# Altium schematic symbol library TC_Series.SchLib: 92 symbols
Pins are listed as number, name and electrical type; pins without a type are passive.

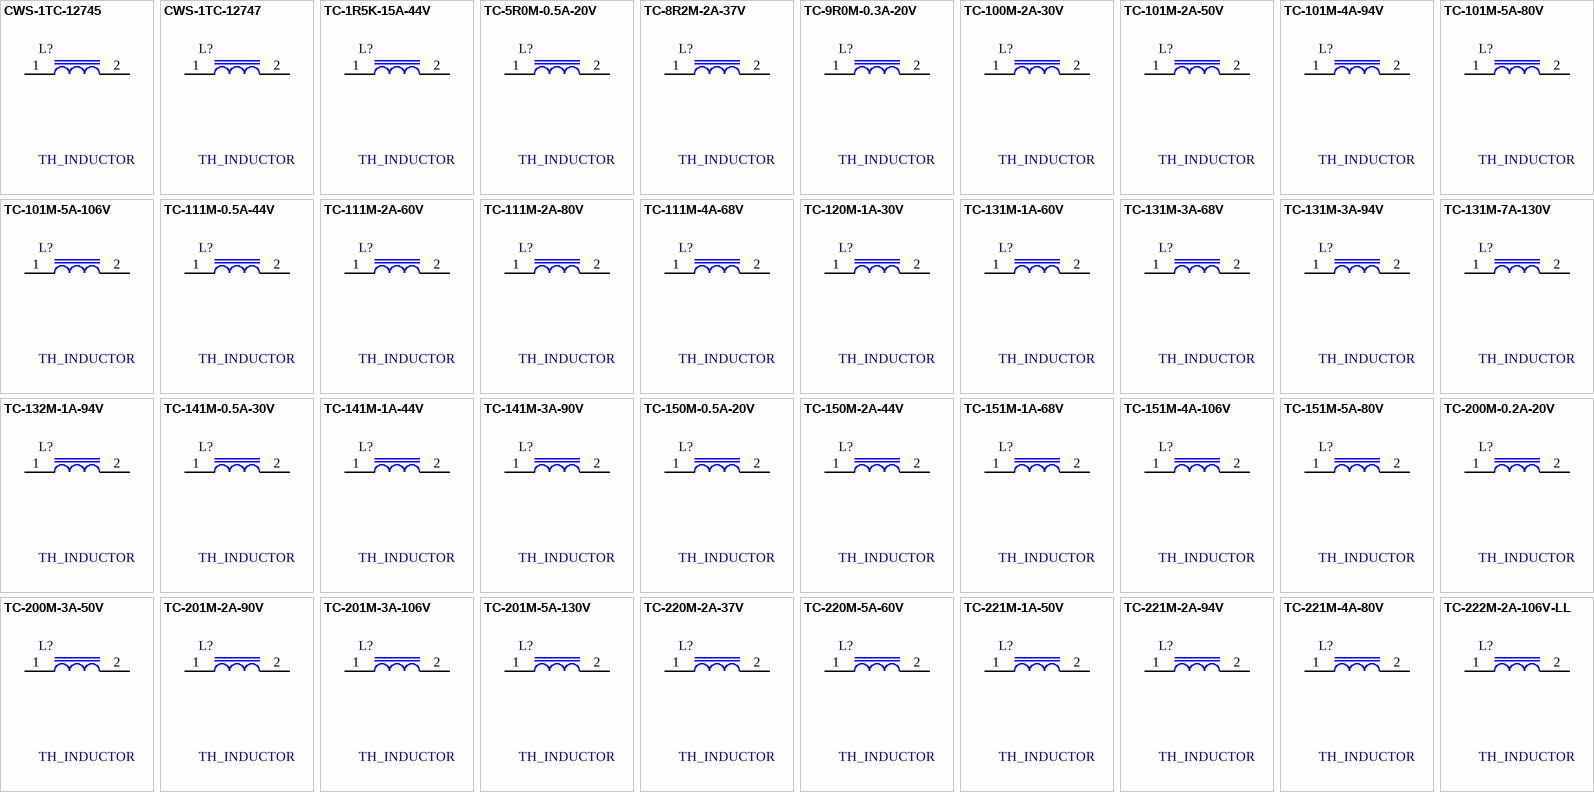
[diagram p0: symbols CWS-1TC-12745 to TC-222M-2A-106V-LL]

## CWS-1TC-12745
designator L?, comment TH_INDUCTOR
POWER INDUCTOR 1 A, 220 uH, 200 mOhms, OD 17.6 mm, HT 8.63 mm; Manufacturer #1: CWS; OD: 17.6 mm; Current: 1 A; Inductance: 220 uH
footprint CWS-1TC-12745
pins: 1, 2

## CWS-1TC-12747
designator L?, comment TH_INDUCTOR
POWER INDUCTOR 1 A, 680 uH, 330 mOhms, OD 18.52 mm, HT 10.87 mm; Manufacturer #1: CWS; Current: 1 A; Inductance: 680 uH
footprint CWS-1TC-12747
pins: 1, 2

## TC-1R5K-15A-44V
designator L?, comment TH_INDUCTOR
POWER INDUCTOR 15 A, 1.5 uH, 2 mOhms, OD 17 mm, HT 11 mm; Manufacturer #1: CWS; OD: 17 mm; Current: 15 A; DCR: 2 mOhms; Inductance: 1.5 uH
footprint TC-1R5K-15A-44V
pins: 1, 2

## TC-5R0M-0.5A-20V
designator L?, comment TH_INDUCTOR
POWER INDUCTOR 0.5 A, 5 uH, 63 mOhms, OD 7 mm, HT 3 mm; Manufacturer #1: CWS; OD: 7 mm; Current: 0.5 A; Inductance: 5 uH
footprint TC-5R0M-0.5A-20V
pins: 1, 2

## TC-8R2M-2A-37V
designator L?, comment TH_INDUCTOR
POWER INDUCTOR 2 A, 8.2 uH, 13 mOhms, OD 12 mm, HT 6 mm; Manufacturer #1: CWS; OD: 12 mm; Current: 2 A; Inductance: 8.2 uH
footprint TC-8R2M-2A-37V
pins: 1, 2

## TC-9R0M-0.3A-20V
designator L?, comment TH_INDUCTOR
POWER INDUCTOR 0.3 A, 9 uH, 95 mOhms, OD 7 mm, HT 3 mm; Manufacturer #1: CWS; OD: 7 mm; Current: 0.3 A; Inductance: 9 uH
footprint TC-9R0M-0.3A-20V
pins: 1, 2

## TC-100M-2A-30V
designator L?, comment TH_INDUCTOR
POWER INDUCTOR 2 A, 10 uH, 24 mOhms, OD 10 mm, HT 6 mm; Manufacturer #1: CWS; OD: 10 mm; Current: 2 A; Inductance: 10 uH
footprint TC-100M-2A-30V
pins: 1, 2

## TC-101M-2A-50V
designator L?, comment TH_INDUCTOR
POWER INDUCTOR 2 A, 100 uH, 99 mOhms, OD 15 mm, HT 8 mm; Manufacturer #1: CWS; OD: 15 mm; Current: 2 A; Inductance: 100 uH
footprint TC-101M-2A-50V
pins: 1, 2

## TC-101M-4A-94V
designator L?, comment TH_INDUCTOR
POWER INDUCTOR 4 A, 100 uH, 27 mOhms, OD 28 mm, HT 13 mm; Manufacturer #1: CWS; OD: 28 mm; Current: 4 A; Inductance: 100 uH
footprint TC-101M-4A-94V
pins: 1, 2

## TC-101M-5A-80V
designator L?, comment TH_INDUCTOR
POWER INDUCTOR 5 A, 100 uH, 38 mOhms, OD 24 mm, HT 11 mm; Manufacturer #1: CWS; OD: 24 mm; Current: 5 A; Inductance: 100 uH
footprint TC-101M-5A-80V
pins: 1, 2

## TC-101M-5A-106V
designator L?, comment TH_INDUCTOR
POWER INDUCTOR 5 A, 100 uH, 22 mOhms, OD 31 mm, HT 16 mm; Manufacturer #1: CWS; OD: 31 mm; Current: 5 A; Inductance: 100 uH
footprint TC-101M-5A-106V
pins: 1, 2

## TC-111M-0.5A-44V
designator L?, comment TH_INDUCTOR
POWER INDUCTOR 0.5 A, 110 uH, 149 mOhms, OD 13 mm, HT 6 mm; Manufacturer #1: CWS; OD: 13 mm; Current: 0.5 A; Inductance: 110 uH
footprint TC-111M-0.5A-44V
pins: 1, 2

## TC-111M-2A-60V
designator L?, comment TH_INDUCTOR
POWER INDUCTOR 2 A, 110 uH, 67 mOhms, OD 18 mm, HT 10 mm; Manufacturer #1: CWS; OD: 18 mm; Current: 2 A; Inductance: 110 uH
footprint TC-111M-2A-60V
pins: 1, 2

## TC-111M-2A-80V
designator L?, comment TH_INDUCTOR
POWER INDUCTOR 2 A, 110 uH, 40 mOhms, OD 23 mm, HT 9 mm; Manufacturer #1: CWS; OD: 23 mm; Current: 2 A; Inductance: 110 uH
footprint TC-111M-2A-80V
pins: 1, 2

## TC-111M-4A-68V
designator L?, comment TH_INDUCTOR
POWER INDUCTOR 4 A, 110 uH, 56 mOhms, OD 21 mm, HT 9 mm; Manufacturer #1: CWS; OD: 21 mm; Current: 4 A; Inductance: 110 uH
footprint TC-111M-4A-68V
pins: 1, 2

## TC-120M-1A-30V
designator L?, comment TH_INDUCTOR
POWER INDUCTOR 1 A, 12 uH, 28 mOhms, OD 9.5 mm, HT 5 mm; Manufacturer #1: CWS; OD: 9.5 mm; Current: 1 A; Inductance: 12 uH
footprint TC-120M-1A-30V
pins: 1, 2

## TC-131M-1A-60V
designator L?, comment TH_INDUCTOR
POWER INDUCTOR 1 A, 130 uH, 78 mOhms, OD 17 mm, HT 8 mm; Manufacturer #1: CWS; OD: 17 mm; Current: 1 A; Inductance: 130 uH
footprint TC-131M-1A-60V
pins: 1, 2

## TC-131M-3A-68V
designator L?, comment TH_INDUCTOR
POWER INDUCTOR 3 A, 130 uH, 73 mOhms, OD 21 mm, HT 9 mm; Manufacturer #1: CWS; OD: 21 mm; Current: 3 A; Inductance: 130 uH
footprint TC-131M-3A-68V
pins: 1, 2

## TC-131M-3A-94V
designator L?, comment TH_INDUCTOR
POWER INDUCTOR 3 A, 130 uH, 32 mOhms, OD 28.5 mm, HT 13 mm; Manufacturer #1: CWS; OD: 28.5 mm; Current: 3 A; Inductance: 130 uH
footprint TC-131M-3A-94V
pins: 1, 2

## TC-131M-7A-130V
designator L?, comment TH_INDUCTOR
POWER INDUCTOR 7 A, 130 uH, 24 mOhms, OD 38 mm, HT 16 mm; Manufacturer #1: CWS; OD: 38 mm; Current: 7 A; Inductance: 130 uH
footprint TC-131M-7A-130V
pins: 1, 2

## TC-132M-1A-94V
designator L?, comment TH_INDUCTOR
POWER INDUCTOR 1 A, 1300 uH, 396 mOhms, OD 27 mm, HT 11 mm; Manufacturer #1: CWS; OD: 27 mm; Current: 1 A; Inductance: 1300 uH
footprint TC-132M-1A-94V
pins: 1, 2

## TC-141M-0.5A-30V
designator L?, comment TH_INDUCTOR
POWER INDUCTOR 0.5 A, 140 uH, 52 mOhms, OD 9.5 mm, HT 5 mm; Manufacturer #1: CWS; OD: 9.5 mm; Current: 0.5 A; Inductance: 140 uH
footprint TC-141M-0.5A-30V
pins: 1, 2

## TC-141M-1A-44V
designator L?, comment TH_INDUCTOR
POWER INDUCTOR 1 A, 140 uH, 282 mOhms, OD 13 mm, HT 6.5 mm; Manufacturer #1: CWS; OD: 13 mm; Current: 1 A; Inductance: 140 uH
footprint TC-141M-1A-44V
pins: 1, 2

## TC-141M-3A-90V
designator L?, comment TH_INDUCTOR
POWER INDUCTOR 3 A, 140 uH, 36 mOhms, OD 26 mm, HT 12 mm; Manufacturer #1: CWS; OD: 26 mm; Current: 3 A; Inductance: 140 uH
footprint TC-141M-3A-90V
pins: 1, 2

## TC-150M-0.5A-20V
designator L?, comment TH_INDUCTOR
POWER INDUCTOR 0.5 A, 15 uH, 158 mOhms, OD 6 mm, HT 3 mm; Manufacturer #1: CWS; OD: 6 mm; Current: 0.5 A; Inductance: 15 uH
footprint TC-150M-0.5A-20V
pins: 1, 2

## TC-150M-2A-44V
designator L?, comment TH_INDUCTOR
POWER INDUCTOR 2 A, 15 uH, 17 mOhms, OD 13 mm, HT 6.5 mm; Manufacturer #1: CWS; OD: 13 mm; Current: 2 A; Inductance: 15 uH
footprint TC-150M-2A-44V
pins: 1, 2

## TC-151M-1A-68V
designator L?, comment TH_INDUCTOR
POWER INDUCTOR 1 A, 150 uH, 75 mOhms, OD 21 mm, HT 8 mm; Manufacturer #1: CWS; OD: 21 mm; Current: 1 A; Inductance: 150 uH
footprint TC-151M-1A-68V
pins: 1, 2

## TC-151M-4A-106V
designator L?, comment TH_INDUCTOR
POWER INDUCTOR 4 A, 150 uH, 33 mOhms, OD 31 mm, HT 16 mm; Manufacturer #1: CWS; OD: 31 mm; Current: 4 A; Inductance: 150 uH
footprint TC-151M-4A-106V
pins: 1, 2

## TC-151M-5A-80V
designator L?, comment TH_INDUCTOR
POWER INDUCTOR 5 A, 150 uH, 38 mOhms, OD 24 mm, HT 11 mm; Manufacturer #1: CWS; OD: 24 mm; Current: 5 A; Inductance: 150 uH
footprint TC-151M-5A-80V
pins: 1, 2

## TC-200M-0.2A-20V
designator L?, comment TH_INDUCTOR
POWER INDUCTOR 0.2 A, 20 uH, 190 mOhms, OD 6 mm, HT 3 mm; Manufacturer #1: CWS; OD: 6 mm; Current: 0.2 A; Inductance: 20 uH
footprint TC-200M-0.2A-20V
pins: 1, 2

## TC-200M-3A-50V
designator L?, comment TH_INDUCTOR
POWER INDUCTOR 3 A, 20 uH, 18 mOhms, OD 15 mm, HT 7 mm; Manufacturer #1: CWS; OD: 15 mm; Current: 3 A; Inductance: 20 uH
footprint TC-200M-3A-50V
pins: 1, 2

## TC-201M-2A-90V
designator L?, comment TH_INDUCTOR
POWER INDUCTOR 2 A, 200 uH, 52 mOhms, OD 26 mm, HT 12 mm; Manufacturer #1: CWS; OD: 26 mm; Current: 2 A; Inductance: 200 uH
footprint TC-201M-2A-90V
pins: 1, 2

## TC-201M-3A-106V
designator L?, comment TH_INDUCTOR
POWER INDUCTOR 3 A, 200 uH, 46 mOhms, OD 31 mm, HT 15 mm; Manufacturer #1: CWS; OD: 31 mm; Current: 3 A; Inductance: 200 uH
footprint TC-201M-3A-106V
pins: 1, 2

## TC-201M-5A-130V
designator L?, comment TH_INDUCTOR
POWER INDUCTOR 5 A, 200 uH, 30 mOhms, OD 38.5 mm, HT 17.5 mm; Manufacturer #1: CWS; OD: 38.5 mm; Current: 5 A; Inductance: 200 uH
footprint TC-201M-5A-130V
pins: 1, 2

## TC-220M-2A-37V
designator L?, comment TH_INDUCTOR
POWER INDUCTOR 2 A, 22 uH, 47 mOhms, OD 12 mm, HT 5.5 mm; Manufacturer #1: CWS; OD: 12 mm; Current: 2 A; Inductance: 22 uH
footprint TC-220M-2A-37V
pins: 1, 2

## TC-220M-5A-60V
designator L?, comment TH_INDUCTOR
POWER INDUCTOR 5 A, 22 uH, 13 mOhms, OD 18 mm, HT 10 mm; Manufacturer #1: CWS; OD: 18 mm; Current: 5 A; Inductance: 22 uH
footprint TC-220M-5A-60V
pins: 1, 2

## TC-221M-1A-50V
designator L?, comment TH_INDUCTOR
POWER INDUCTOR 1 A, 220 uH, 145 mOhms, OD 14 mm, HT 7 mm; Manufacturer #1: CWS; OD: 14 mm; Current: 1 A; Inductance: 220 uH
footprint TC-221M-1A-50V
pins: 1, 2

## TC-221M-2A-94V
designator L?, comment TH_INDUCTOR
POWER INDUCTOR 2 A, 220 uH, 60 mOhms, OD 27 mm, HT 12 mm; Manufacturer #1: CWS; OD: 27 mm; Current: 2 A; Inductance: 220 uH
footprint TC-221M-2A-94V
pins: 1, 2

## TC-221M-4A-80V
designator L?, comment TH_INDUCTOR
POWER INDUCTOR 4 A, 220 uH, 49 mOhms, OD 24 mm, HT 11 mm; Manufacturer #1: CWS; OD: 24 mm; Current: 4 A; Inductance: 220 uH
footprint TC-221M-4A-80V
pins: 1, 2

## TC-222M-2A-106V-LL
designator L?, comment TH_INDUCTOR
POWER INDUCTOR 2 A, 2200 uH, 375 mOhms, OD 31 mm, HT 16 mm; Manufacturer #1: CWS; OD: 31 mm; Current: 2 A; Inductance: 2200 uH
footprint TC-222M-2A-106V-LL
pins: 1, 2

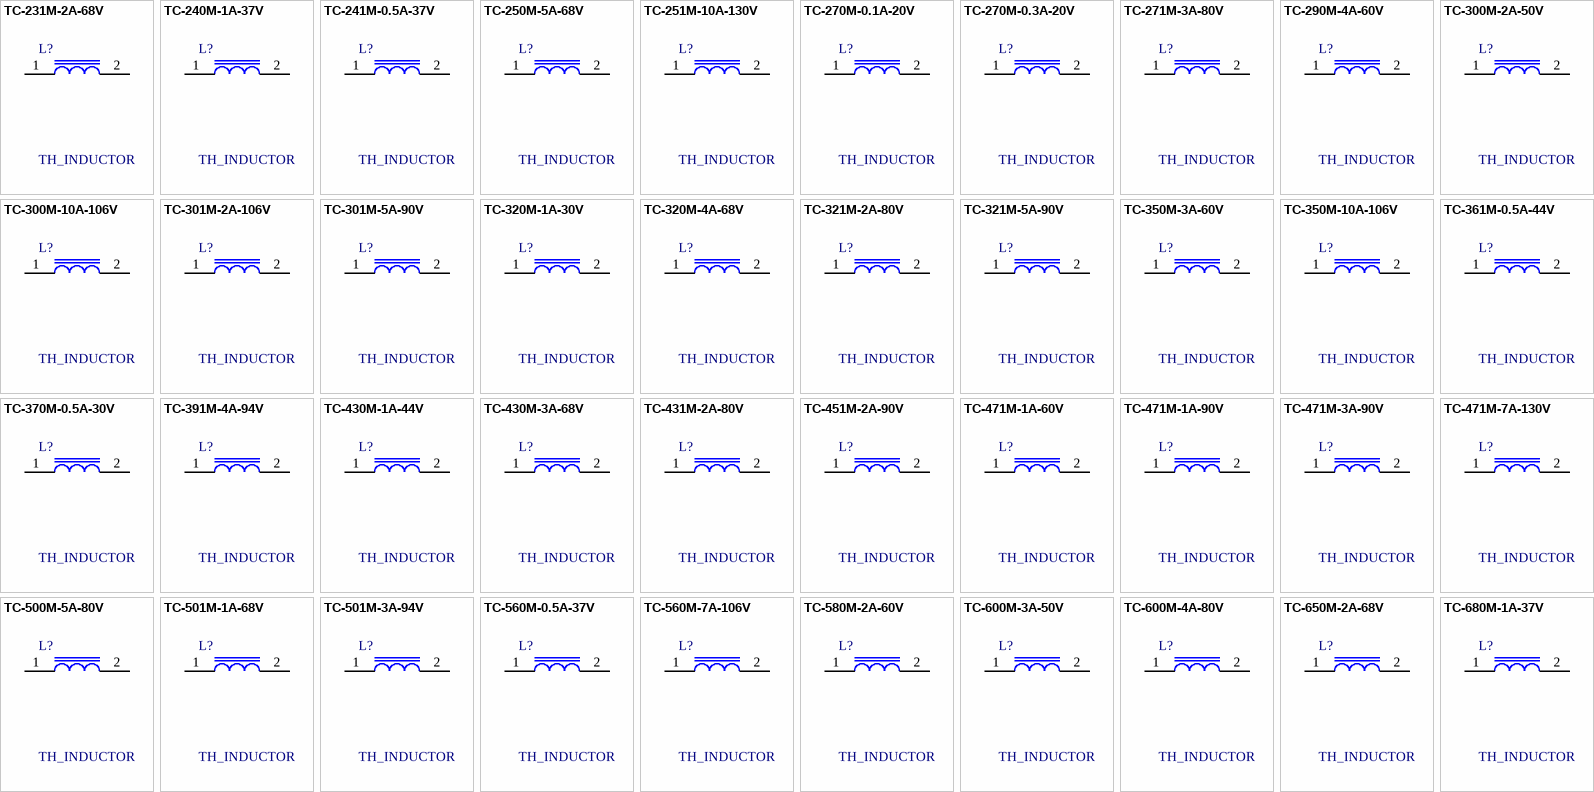
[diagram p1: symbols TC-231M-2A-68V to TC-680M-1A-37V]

## TC-231M-2A-68V
designator L?, comment TH_INDUCTOR
POWER INDUCTOR 2 A, 230 uH, 170 mOhms, OD 21 mm, HT 9 mm; Manufacturer #1: CWS; OD: 21 mm; Current: 2 A; Inductance: 230 uH
footprint TC-231M-2A-68V
pins: 1, 2

## TC-240M-1A-37V
designator L?, comment TH_INDUCTOR
POWER INDUCTOR 1 A, 24 uH, 47 mOhms, OD 11.5 mm, HT 5 mm; Manufacturer #1: CWS; OD: 11.5 mm; Current: 1 A; Inductance: 24 uH
footprint TC-240M-1A-37V
pins: 1, 2

## TC-241M-0.5A-37V
designator L?, comment TH_INDUCTOR
POWER INDUCTOR 0.5 A, 240 uH, 495 mOhms, OD 10.7 mm, HT 5.34 mm; Manufacturer #1: CWS; OD: 10.7 mm; Current: 0.5 A; Inductance: 240 uH
footprint TC-241M-0.5A-37V
pins: 1, 2

## TC-250M-5A-68V
designator L?, comment TH_INDUCTOR
POWER INDUCTOR 5 A, 25 uH, 14 mOhms, OD 21 mm, HT 8 mm; Manufacturer #1: CWS; OD: 21 mm; Current: 5 A; Inductance: 25 uH
footprint TC-250M-5A-68V
pins: 1, 2

## TC-251M-10A-130V
designator L?, comment TH_INDUCTOR
POWER INDUCTOR 10 A, 250 uH, 34 mOhms, OD 40 mm, HT 20 mm; Manufacturer #1: CWS; OD: 40 mm; Current: 10 A; Inductance: 250 uH
footprint TC-251M-10A-130V
pins: 1, 2

## TC-270M-0.1A-20V
designator L?, comment TH_INDUCTOR
POWER INDUCTOR 0.1 A, 27 uH, 255 mOhms, OD 6 mm, HT 2.8 mm; Manufacturer #1: CWS; OD: 6 mm; Current: 0.1 A; Inductance: 27 uH
footprint TC-270M-0.1A-20V
pins: 1, 2

## TC-270M-0.3A-20V
designator L?, comment TH_INDUCTOR
POWER INDUCTOR 0.3 A, 27 uH, 259 mOhms, OD 6 mm, HT 3 mm; Manufacturer #1: CWS; OD: 6 mm; Current: 0.3 A; Inductance: 27 uH
footprint TC-270M-0.3A-20V
pins: 1, 2

## TC-271M-3A-80V
designator L?, comment TH_INDUCTOR
POWER INDUCTOR 3 A, 270 uH, 114 mOhms, OD 24 mm, HT 11 mm; Manufacturer #1: CWS; OD: 24 mm; Current: 3 A; Inductance: 270 uH
footprint TC-271M-3A-80V
pins: 1, 2

## TC-290M-4A-60V
designator L?, comment TH_INDUCTOR
POWER INDUCTOR 4 A, 29 uH, 17 mOhms, OD 18 mm, HT 10 mm; Manufacturer #1: CWS; OD: 18 mm; Current: 4 A; Inductance: 29 uH
footprint TC-290M-4A-60V
pins: 1, 2

## TC-300M-2A-50V
designator L?, comment TH_INDUCTOR
POWER INDUCTOR 2 A, 30 uH, 26 mOhms, OD 15 mm, HT 7 mm; Manufacturer #1: CWS; OD: 15 mm; Current: 2 A; Inductance: 30 uH
footprint TC-300M-2A-50V
pins: 1, 2

## TC-300M-10A-106V
designator L?, comment TH_INDUCTOR
POWER INDUCTOR 10 A, 30 uH, 8 mOhms, OD 33 mm, HT 17 mm; Manufacturer #1: CWS; OD: 33 mm; Current: 10 A; DCR: 8 mOhms; Inductance: 30 uH
footprint TC-300M-10A-106V
pins: 1, 2

## TC-301M-2A-106V
designator L?, comment TH_INDUCTOR
POWER INDUCTOR 2 A, 300 uH, 70 mOhms, OD 32 mm, HT 15 mm; Manufacturer #1: CWS; OD: 32 mm; Current: 2 A; Inductance: 300 uH
footprint TC-301M-2A-106V
pins: 1, 2

## TC-301M-5A-90V
designator L?, comment TH_INDUCTOR
POWER INDUCTOR 5 A, 300 uH, 68 mOhms, OD 26 mm, HT 14 mm; Manufacturer #1: CWS; OD: 26 mm; Current: 5 A; Inductance: 300 uH
footprint TC-301M-5A-90V
pins: 1, 2

## TC-320M-1A-30V
designator L?, comment TH_INDUCTOR
POWER INDUCTOR 1 A, 32 uH, 93 mOhms, OD 9.5 mm, HT 5.5 mm; Manufacturer #1: CWS; OD: 9.5 mm; Current: 1 A; Inductance: 32 uH
footprint TC-320M-1A-30V
pins: 1, 2

## TC-320M-4A-68V
designator L?, comment TH_INDUCTOR
POWER INDUCTOR 4 A, 32 uH, 17 mOhms, OD 21 mm, HT 8 mm; Manufacturer #1: CWS; OD: 21 mm; Current: 4 A; Inductance: 32 uH
footprint TC-320M-4A-68V
pins: 1, 2

## TC-321M-2A-80V
designator L?, comment TH_INDUCTOR
POWER INDUCTOR 2 A, 320 uH, 157 mOhms, OD 23 mm, HT 10 mm; Manufacturer #1: CWS; OD: 23 mm; Current: 2 A; Inductance: 320 uH
footprint TC-321M-2A-80V
pins: 1, 2

## TC-321M-5A-90V
designator L?, comment TH_INDUCTOR
POWER INDUCTOR 5 A, 320 uH, 52 mOhms, OD 29.2 mm, HT 16.5 mm; Manufacturer #1: CWS; OD: 29.2 mm; Current: 5 A; Inductance: 320 uH
footprint TC-321M-5A-90V
pins: 1, 2

## TC-350M-3A-60V
designator L?, comment TH_INDUCTOR
POWER INDUCTOR 3 A, 35 uH, 21 mOhms, OD 18 mm, HT 9 mm; Manufacturer #1: CWS; OD: 18 mm; Current: 3 A; Inductance: 35 uH
footprint TC-350M-3A-60V
pins: 1, 2

## TC-350M-10A-106V
designator L?, comment TH_INDUCTOR
POWER INDUCTOR 10 A, 35 uH, 9 mOhms, OD 32 mm, HT 16 mm; Manufacturer #1: CWS; OD: 32 mm; Current: 10 A; DCR: 9 mOhms; Inductance: 35 uH
footprint TC-350M-10A-106V
pins: 1, 2

## TC-361M-0.5A-44V
designator L?, comment TH_INDUCTOR
POWER INDUCTOR 0.5 A, 360 uH, 325 mOhms, OD 12.5 mm, HT 5.5 mm; Manufacturer #1: CWS; OD: 12.5 mm; Current: 0.5 A; Inductance: 360 uH
footprint TC-361M-0.5A-44V
pins: 1, 2

## TC-370M-0.5A-30V
designator L?, comment TH_INDUCTOR
POWER INDUCTOR 0.5 A, 37 uH, 110 mOhms, OD 9.5 mm, HT 5 mm; Manufacturer #1: CWS; OD: 9.5 mm; Current: 0.5 A; Inductance: 37 uH
footprint TC-370M-0.5A-30V
pins: 1, 2

## TC-391M-4A-94V
designator L?, comment TH_INDUCTOR
POWER INDUCTOR 4 A, 390 uH, 100 mOhms, OD 27 mm, HT 12 mm; Manufacturer #1: CWS; OD: 27 mm; Current: 4 A; Inductance: 390 uH
footprint TC-391M-4A-94V
pins: 1, 2

## TC-430M-1A-44V
designator L?, comment TH_INDUCTOR
POWER INDUCTOR 1 A, 43 uH, 60 mOhms, OD 13 mm, HT 6 mm; Manufacturer #1: CWS; OD: 13 mm; Current: 1 A; Inductance: 43 uH
footprint TC-430M-1A-44V
pins: 1, 2

## TC-430M-3A-68V
designator L?, comment TH_INDUCTOR
POWER INDUCTOR 3 A, 43 uH, 24 mOhms, OD 21 mm, HT 8 mm; Manufacturer #1: CWS; OD: 21 mm; Current: 3 A; Inductance: 43 uH
footprint TC-430M-3A-68V
pins: 1, 2

## TC-431M-2A-80V
designator L?, comment TH_INDUCTOR
POWER INDUCTOR 2 A, 430 uH, 185 mOhms, OD 24 mm, HT 11 mm; Manufacturer #1: CWS; OD: 24 mm; Current: 2 A; Inductance: 430 uH
footprint TC-431M-2A-80V
pins: 1, 2

## TC-451M-2A-90V
designator L?, comment TH_INDUCTOR
POWER INDUCTOR 2 A, 450 uH, 118 mOhms, OD 25 mm, HT 13 mm; Manufacturer #1: CWS; OD: 25 mm; Current: 2 A; Inductance: 450 uH
footprint TC-451M-2A-90V
pins: 1, 2

## TC-471M-1A-60V
designator L?, comment TH_INDUCTOR
POWER INDUCTOR 1 A, 470 uH, 33 mOhms, OD 17 mm, HT 8 mm; Manufacturer #1: CWS; OD: 17 mm; Current: 1 A; Inductance: 470 uH
footprint TC-471M-1A-60V
pins: 1, 2

## TC-471M-1A-90V
designator L?, comment TH_INDUCTOR
POWER INDUCTOR 1 A, 470 uH, 253 mOhms, OD 25 mm, HT 11 mm; Manufacturer #1: CWS; OD: 25 mm; Current: 1 A; Inductance: 470 uH
footprint TC-471M-1A-90V
pins: 1, 2

## TC-471M-3A-90V
designator L?, comment TH_INDUCTOR
POWER INDUCTOR 3 A, 470 uH, 118 mOhms, OD 27 mm, HT 14 mm; Manufacturer #1: CWS; OD: 27 mm; Current: 3 A; Inductance: 470 uH
footprint TC-471M-3A-90V
pins: 1, 2

## TC-471M-7A-130V
designator L?, comment TH_INDUCTOR
POWER INDUCTOR 7 A, 470 uH, 62 mOhms, OD 38 mm, HT 18 mm; Manufacturer #1: CWS; OD: 38 mm; Current: 7 A; Inductance: 470 uH
footprint TC-471M-7A-130V
pins: 1, 2

## TC-500M-5A-80V
designator L?, comment TH_INDUCTOR
POWER INDUCTOR 5 A, 50 uH, 16 mOhms, OD 24 mm, HT 10 mm; Manufacturer #1: CWS; OD: 24 mm; Current: 5 A; Inductance: 50 uH
footprint TC-500M-5A-80V
pins: 1, 2

## TC-501M-1A-68V
designator L?, comment TH_INDUCTOR
POWER INDUCTOR 1 A, 500 uH, 363 mOhms, OD 21 mm, HT 9 mm; Manufacturer #1: CWS; OD: 21 mm; Current: 1 A; Inductance: 500 uH
footprint TC-501M-1A-68V
pins: 1, 2

## TC-501M-3A-94V
designator L?, comment TH_INDUCTOR
POWER INDUCTOR 3 A, 500 uH, 129 mOhms, OD 27 mm, HT 12 mm; Manufacturer #1: CWS; OD: 27 mm; Current: 3 A; Inductance: 500 uH
footprint TC-501M-3A-94V
pins: 1, 2

## TC-560M-0.5A-37V
designator L?, comment TH_INDUCTOR
POWER INDUCTOR 0.5 A, 56 uH, 155 mOhms, OD 11 mm, HT 5 mm; Manufacturer #1: CWS; OD: 11 mm; Current: 0.5 A; Inductance: 56 uH
footprint TC-560M-0.5A-37V
pins: 1, 2

## TC-560M-7A-106V
designator L?, comment TH_INDUCTOR
POWER INDUCTOR 7 A, 56 uH, 13 mOhms, OD 31.5 mm, HT 17 mm; Manufacturer #1: CWS; OD: 31.5 mm; Current: 7 A; Inductance: 56 uH
footprint TC-560M-7A-106V
pins: 1, 2

## TC-580M-2A-60V
designator L?, comment TH_INDUCTOR
POWER INDUCTOR 2 A, 58 uH, 34 mOhms, OD 17 mm, HT 8 mm; Manufacturer #1: CWS; OD: 17 mm; Current: 2 A; Inductance: 58 uH
footprint TC-580M-2A-60V
pins: 1, 2

## TC-600M-3A-50V
designator L?, comment TH_INDUCTOR
POWER INDUCTOR 3 A, 60 uH, 52 mOhms, OD 15 mm, HT 9 mm; Manufacturer #1: CWS; OD: 15 mm; Current: 3 A; Inductance: 60 uH
footprint TC-600M-3A-50V
pins: 1, 2

## TC-600M-4A-80V
designator L?, comment TH_INDUCTOR
POWER INDUCTOR 4 A, 60 uH, 24 mOhms, OD 24 mm, HT 10 mm; Manufacturer #1: CWS; OD: 24 mm; Current: 4 A; Inductance: 60 uH
footprint TC-600M-4A-80V
pins: 1, 2

## TC-650M-2A-68V
designator L?, comment TH_INDUCTOR
POWER INDUCTOR 2 A, 65 uH, 38 mOhms, OD 21 mm, HT 8 mm; Manufacturer #1: CWS; OD: 21 mm; Current: 2 A; Inductance: 65 uH
footprint TC-650M-2A-68V
pins: 1, 2

## TC-680M-1A-37V
designator L?, comment TH_INDUCTOR
POWER INDUCTOR 1 A, 68 uH, 108 mOhms, OD 11.5 mm, HT 5.5 mm; Manufacturer #1: CWS; OD: 11.5 mm; Current: 1 A; Inductance: 68 uH
footprint TC-680M-1A-37V
pins: 1, 2

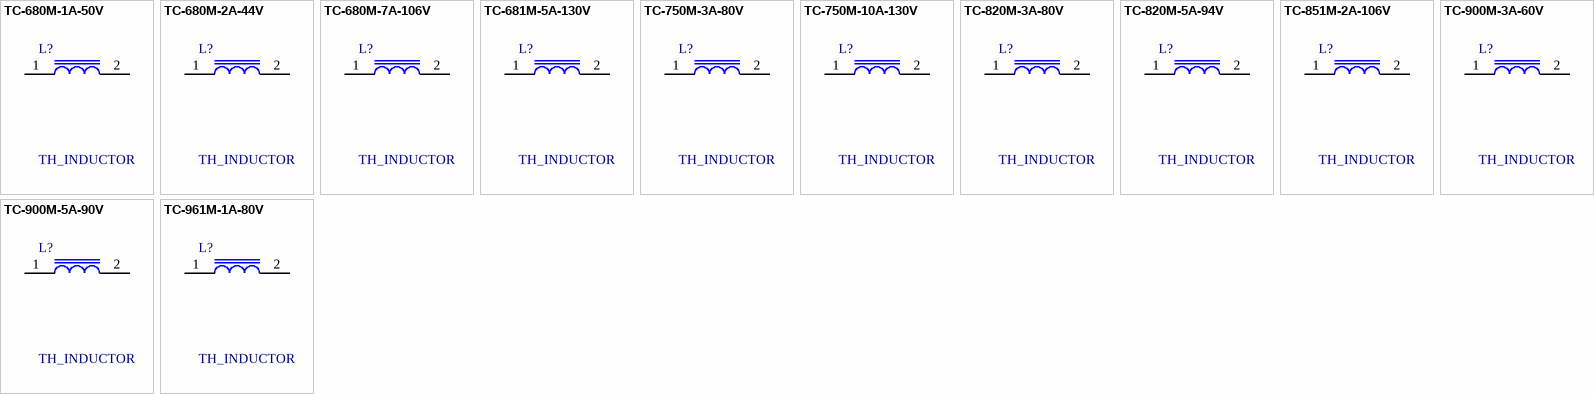
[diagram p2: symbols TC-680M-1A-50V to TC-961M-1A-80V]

## TC-680M-1A-50V
designator L?, comment TH_INDUCTOR
POWER INDUCTOR 1 A, 68 uH, 54 mOhms, OD 14 mm, HT 6 mm; Manufacturer #1: CWS; OD: 14 mm; Current: 1 A; Inductance: 68 uH
footprint TC-680M-1A-50V
pins: 1, 2

## TC-680M-2A-44V
designator L?, comment TH_INDUCTOR
POWER INDUCTOR 2 A, 68 uH, 40 mOhms, OD 13.5 mm, HT 7.5 mm; Manufacturer #1: CWS; OD: 13.5 mm; Current: 2 A; Inductance: 68 uH
footprint TC-680M-2A-44V
pins: 1, 2

## TC-680M-7A-106V
designator L?, comment TH_INDUCTOR
POWER INDUCTOR 7 A, 68 uH, 13 mOhms, OD 32 mm, HT 115.5 mm; Manufacturer #1: CWS; OD: 32 mm; Current: 7 A; Inductance: 68 uH
footprint TC-680M-7A-106V
pins: 1, 2

## TC-681M-5A-130V
designator L?, comment TH_INDUCTOR
POWER INDUCTOR 5 A, 680 uH, 99 mOhms, OD 37.5 mm, HT 17.5 mm; Manufacturer #1: CWS; OD: 37.5 mm; Current: 5 A; Inductance: 680 uH
footprint TC-681M-5A-130V
pins: 1, 2

## TC-750M-3A-80V
designator L?, comment TH_INDUCTOR
POWER INDUCTOR 3 A, 75 uH, 26 mOhms, OD 23 mm, HT 10 mm; Manufacturer #1: CWS; OD: 23 mm; Current: 3 A; Inductance: 75 uH
footprint TC-750M-3A-80V
pins: 1, 2

## TC-750M-10A-130V
designator L?, comment TH_INDUCTOR
POWER INDUCTOR 10 A, 75 uH, 11 mOhms, OD 40 mm, HT 19 mm; Manufacturer #1: CWS; OD: 40 mm; Current: 10 A; Inductance: 75 uH
footprint TC-750M-10A-130V
pins: 1, 2

## TC-820M-3A-80V
designator L?, comment TH_INDUCTOR
POWER INDUCTOR 3 A, 82 uH, 28 mOhms, OD 24 mm, HT 10 mm; Manufacturer #1: CWS; OD: 24 mm; Current: 3 A; Inductance: 82 uH
footprint TC-820M-3A-80V
pins: 1, 2

## TC-820M-5A-94V
designator L?, comment TH_INDUCTOR
POWER INDUCTOR 5 A, 82 uH, 24 mOhms, OD 28 mm, HT 12 mm; Manufacturer #1: CWS; OD: 28 mm; Current: 5 A; Inductance: 82 uH
footprint TC-820M-5A-94V
pins: 1, 2

## TC-851M-2A-106V
designator L?, comment TH_INDUCTOR
POWER INDUCTOR 2 A, 850 uH, 180 mOhms, OD 30 mm, HT 15 mm; Manufacturer #1: CWS; OD: 30 mm; Current: 2 A; Inductance: 850 uH
footprint TC-851M-2A-106V
pins: 1, 2

## TC-900M-3A-60V
designator L?, comment TH_INDUCTOR
POWER INDUCTOR 3 A, 90 uH, 48 mOhms, OD 18 mm, HT 10 mm; Manufacturer #1: CWS; OD: 18 mm; Current: 3 A; Inductance: 90 uH
footprint TC-900M-3A-60V
pins: 1, 2

## TC-900M-5A-90V
designator L?, comment TH_INDUCTOR
POWER INDUCTOR 5 A, 90 uH, 22 mOhms, OD 27 mm, HT 13.2 mm; Manufacturer #1: CWS; OD: 27 mm; Current: 5 A; Inductance: 90 uH
footprint TC-900M-5A-90V
pins: 1, 2

## TC-961M-1A-80V
designator L?, comment TH_INDUCTOR
POWER INDUCTOR 1 A, 960 uH, 333 mOhms, OD 28 mm, HT 14 mm; Manufacturer #1: CWS; OD: 28 mm; Current: 1 A; Inductance: 960 uH
footprint TC-961M-1A-80V
pins: 1, 2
